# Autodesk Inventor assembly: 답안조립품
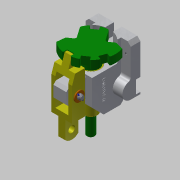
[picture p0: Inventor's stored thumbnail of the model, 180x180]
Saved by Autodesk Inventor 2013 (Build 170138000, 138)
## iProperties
Created: 2016-11
Part Number: 답안조립품
Document SubType Name: Assembly
Designer: Administrator
Author: Administrator
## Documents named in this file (8)
- C:\Users\Administrator\Desktop\답안조립품.iam
- C:\Users\Administrator\Desktop\본체.ipt
- C:\Users\Administrator\Desktop\부시.ipt
- C:\Users\Administrator\Desktop\분할대.ipt
- C:\Users\Administrator\Desktop\분할축.ipt
- C:\Users\Administrator\Desktop\와셔.ipt
- C:\Users\Administrator\Desktop\원통형핀.ipt
- C:\Users\Administrator\Desktop\클레비스핀.ipt
